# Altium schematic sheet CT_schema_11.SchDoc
size 147 x 119 mm
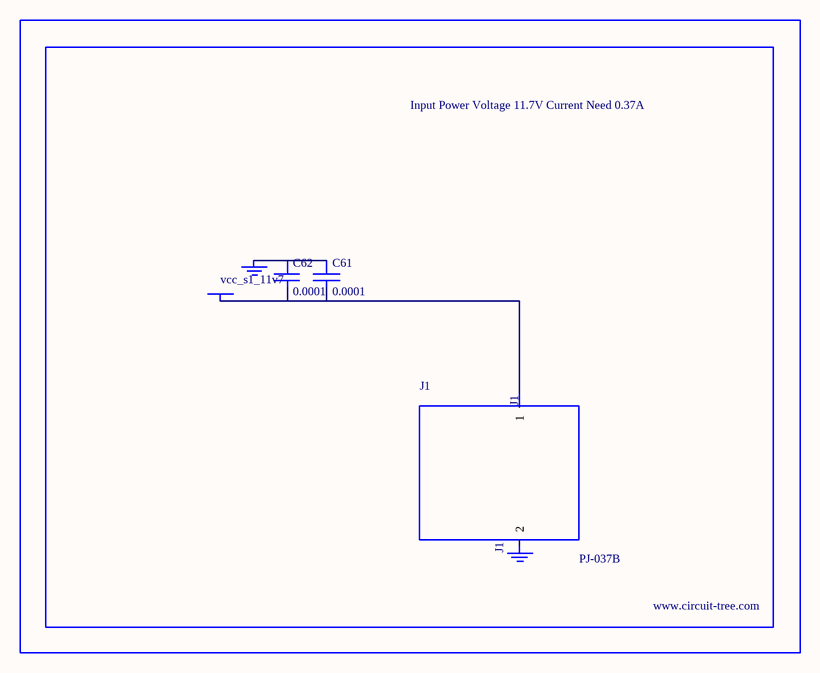
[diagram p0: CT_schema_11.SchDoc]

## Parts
BORDER10  (no value)
C61  0.0001  [EXV-9H]
C62  0.0001  [EXV-9H]
GND_INSTANCE_10_0  (no value)
GND_INSTANCE_10_1  (no value)
J1  PJ-037B  [PJ-037B_PACKAGE]
POWER_INSTANCE_10_0  vcc_s1_11v7

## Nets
NetC61_1: C61.1 C62.1 GND_INSTANCE_10_0.0(GND)
NetC61_2: C61.2 C62.2 J1.1 POWER_INSTANCE_10_0.0(PWR)

Not connected (* = marked no-connect by the designer): GND_INSTANCE_10_1 0(GND); J1 2

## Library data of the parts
BORDER10 = BORDER_PAGE10
C61 C62 = EDK107M035A9HAA
GND_INSTANCE_10_0 GND_INSTANCE_10_1 = GND
POWER_INSTANCE_10_0 = PWR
